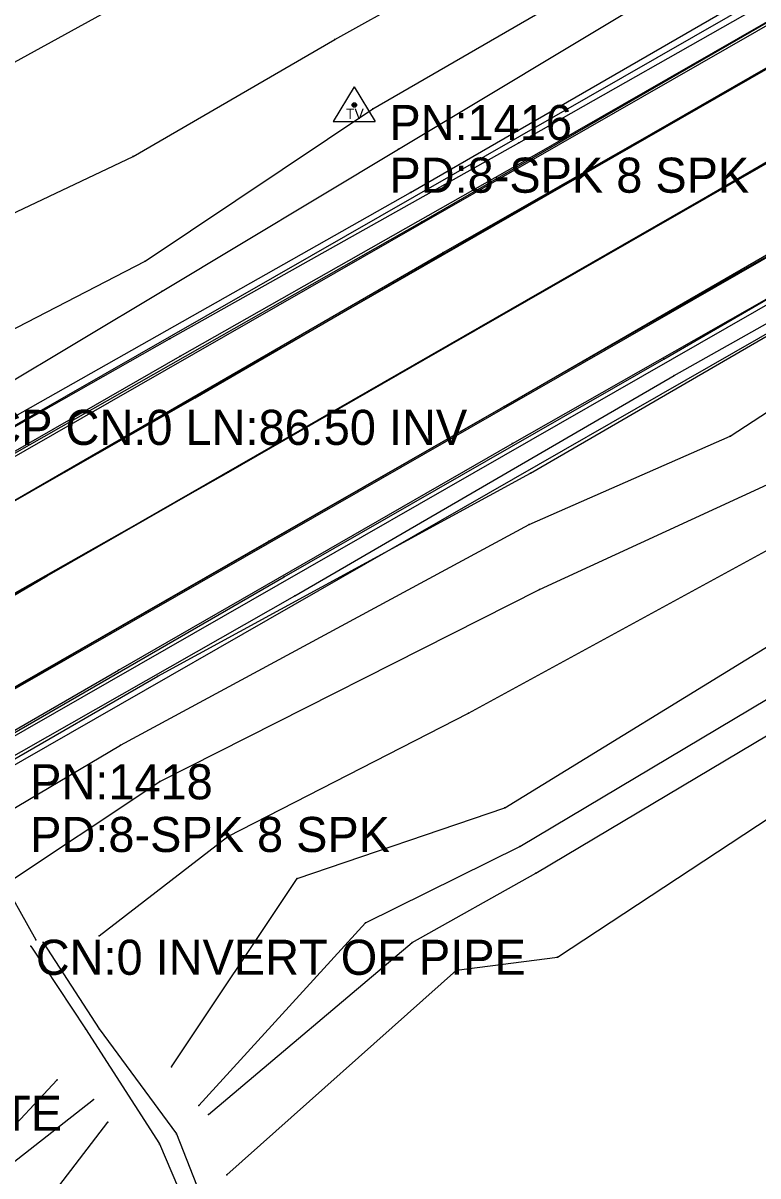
# Model space of a CAD drawing. Extents: x 1419505 to 1434054, y 1956910 to 1968644.
# Drawn here: x 1421962.4 to 1422067.1, y 1958243.6 to 1958407.8 of the extents above; entities that cross this region are included whole.
import ezdxf

# ---------------------------------------------------------------- set-up
doc = ezdxf.new("R2010")
doc.units = 0
for name, color, linetype in [('S_BREAKLINE', 7, 'Continuous'), ('S_CROSS_DRAIN', 7, 'Continuous'), ('S_CROSS_DRAIN_ANNOT', 7, 'Continuous'), ('S_DITCHLINE', 7, 'Continuous'), ('S_DRG_PT_SYM', 7, 'Continuous'), ('S_EDGE_PAVEMENT', 7, 'Continuous'), ('S_GRD_PT_SYM', 7, 'Continuous'), ('S_PAVEMENT_CROWN', 7, 'Continuous'), ('S_RDW_PT_SYM', 7, 'Continuous'), ('S_SECONDARY_CTL', 7, 'Continuous'), ('S_SECONDARY_CTL_ANNOT', 7, 'Continuous'), ('S_SHOULDER', 7, 'Continuous'), ('S_UTILITY_POLE_ANNOT', 7, 'Continuous')]:
    doc.layers.add(name, color=color, linetype=linetype)

msp = doc.modelspace()

# ---------------------------------------------------------------- linework, layer by layer
at = {"layer": 'S_BREAKLINE'}
for p, q in [((1422234.7195, 1958507.1234), (1421697.9208, 1958199.8056)), ((1422256.1529, 1958471.0691), (1421717.7711, 1958162.8162)), ((1422006.7898, 1958405.5229), (1422053.5668, 1958431.4825)), ((1422012.2361, 1958395.6072), (1422059.3222, 1958422.91)), ((1421917.104, 1958378.0281), (1421994.628, 1958420.6969)), ((1422033.0325, 1958390.7609), (1422085.1288, 1958420.3518)), ((1422015.8844, 1958389.8979), (1422062.5334, 1958417.8917)), ((1422017.6015, 1958383.6815), (1422073.1751, 1958415.8125)), ((1421978.0419, 1958388.8168), (1422006.7898, 1958405.5229)), ((1421979.78, 1958373.9038), (1422012.2361, 1958395.6072)), ((1421983.2653, 1958362.8431), (1422033.0325, 1958390.7609)), ((1421982.2072, 1958369.6576), (1422015.8844, 1958389.8979)), ((1421958.5247, 1958379.5882), (1421978.0419, 1958388.8168)), ((1422055.1799, 1958357.6138), (1422103.028, 1958384.7115)), ((1421954.2254, 1958347.8811), (1422017.6015, 1958383.6815)), ((1422063.1634, 1958348.9762), (1422110.2245, 1958379.8242)), ((1422034.6836, 1958343.7029), (1422093.6324, 1958377.9281)), ((1421937.4223, 1958352.1054), (1421979.78, 1958373.9038)), ((1421938.5364, 1958343.5369), (1421982.2072, 1958369.6576)), ((1421931.9739, 1958333.7802), (1421983.2653, 1958362.8431)), ((1422001.1034, 1958326.2257), (1422055.1799, 1958357.6138)), ((1422034.4776, 1958336.4084), (1422063.1634, 1958348.9762)), ((1421981.5771, 1958314.819), (1422034.6836, 1958343.7029)), ((1422035.9747, 1958327.1518), (1422068.4648, 1958342.0838)), ((1421976.2538, 1958304.9524), (1422034.4776, 1958336.4084)), ((1422025.847, 1958309.5217), (1422071.824, 1958334.6333)), ((1421981.8452, 1958299.808), (1422035.9747, 1958327.1518)), ((1421952.7093, 1958298.741), (1422001.1034, 1958326.2257)), ((1422031.0383, 1958296.0688), (1422080.2205, 1958326.2678)), ((1421916.0939, 1958277.0146), (1421981.5771, 1958314.819)), ((1422038.5128, 1958274.7904), (1422097.1516, 1958313.3479)), ((1421991.5588, 1958291.9495), (1422025.847, 1958309.5217)), ((1421948.47, 1958288.4943), (1421976.2538, 1958304.9524)), ((1421952.6123, 1958280.3578), (1421981.8452, 1958299.808)), ((1422001.4264, 1958285.9711), (1422031.0383, 1958296.0688)), ((1421973.2386, 1958277.8106), (1421991.5588, 1958291.9495)), ((1421983.5273, 1958259.1464), (1422001.4264, 1958285.9711)), ((1422024.1189, 1958272.9393), (1422038.5128, 1958274.7904)), ((1421991.4308, 1958243.7604), (1422024.1189, 1958272.9393)), ((1421953.8624, 1958242.9624), (1421967.2182, 1958257.3113))]:
    msp.add_line(p, q, dxfattribs=at)
at = {"layer": 'S_CROSS_DRAIN'}
msp.add_line((1421921.8453, 1958352.7455), (1421964.179, 1958277.2576), dxfattribs=at)
at = {"layer": 'S_DITCHLINE'}
for p, q in [((1422033.1765, 1958290.5544), (1422085.0588, 1958321.4514)), ((1422035.4296, 1958286.7462), (1422088.245, 1958318.1782)), ((1422011.1851, 1958279.6487), (1422033.1765, 1958290.5544)), ((1422017.8235, 1958276.8446), (1422035.4296, 1958286.7462)), ((1421987.4345, 1958253.6431), (1422011.1851, 1958279.6487)), ((1421963.46, 1958276.3395), (1421971.2655, 1958264.5638)), ((1421965.2461, 1958276.8846), (1421973.2396, 1958264.5658)), ((1421988.7896, 1958252.364), (1422017.8235, 1958276.8446)), ((1421971.2655, 1958264.5638), (1421981.7942, 1958248.1677)), ((1421973.2396, 1958264.5658), (1421984.2623, 1958249.5828)), ((1421959.2047, 1958244.1254), (1421972.3946, 1958254.4791)), ((1421963.978, 1958237.6), (1421974.4557, 1958251.2699)), ((1421984.2623, 1958249.5828), (1421988.8426, 1958237.869)), ((1421981.7942, 1958248.1677), (1421986.8055, 1958236.563))]:
    msp.add_line(p, q, dxfattribs=at)
at = {"layer": 'S_DRG_PT_SYM'}
msp.add_lwpolyline([(1421964.179, 1958277.2576), (1421964.179, 1958277.3076), (1421964.179, 1958277.2576), (1421964.129, 1958277.2576), (1421964.179, 1958277.2576), (1421964.179, 1958277.2076), (1421964.179, 1958277.2576), (1421964.229, 1958277.2576)], dxfattribs=at)
at = {"layer": 'S_EDGE_PAVEMENT'}
for p, q in [((1422239.4358, 1958499.3739), (1421702.5421, 1958191.435)), ((1422250.9195, 1958479.1606), (1421712.8678, 1958170.5937)), ((1422037.8508, 1958384.0085), (1422088.5001, 1958413.0854)), ((1422022.2428, 1958375.1419), (1422077.7144, 1958406.7339)), ((1422050.5066, 1958364.4322), (1422098.1177, 1958391.499)), ((1422030.9553, 1958353.2065), (1422088.8241, 1958386.7197)), ((1421986.8895, 1958354.4306), (1422037.8508, 1958384.0085)), ((1421960.3158, 1958339.3426), (1422022.2428, 1958375.1419)), ((1421997.4022, 1958334.0293), (1422050.5066, 1958364.4322)), ((1421937.4303, 1958326.3088), (1421986.8895, 1958354.4306)), ((1421972.0725, 1958319.4363), (1422030.9553, 1958353.2065)), ((1421948.429, 1958305.9944), (1421997.4022, 1958334.0293)), ((1421913.0017, 1958285.5141), (1421972.0725, 1958319.4363))]:
    msp.add_line(p, q, dxfattribs=at)
at = {"layer": 'S_GRD_PT_SYM'}
for points in [[(1422006.7898, 1958405.5229), (1422006.7898, 1958405.5729), (1422006.7898, 1958405.5229), (1422006.7398, 1958405.5229), (1422006.7898, 1958405.5229), (1422006.7898, 1958405.4729), (1422006.7898, 1958405.5229), (1422006.8398, 1958405.5229)], [(1422012.2361, 1958395.6072), (1422012.2361, 1958395.6572), (1422012.2361, 1958395.6072), (1422012.1861, 1958395.6072), (1422012.2361, 1958395.6072), (1422012.2361, 1958395.5572), (1422012.2361, 1958395.6072), (1422012.2861, 1958395.6072)], [(1422033.0325, 1958390.7609), (1422033.0325, 1958390.8109), (1422033.0325, 1958390.7609), (1422032.9825, 1958390.7609), (1422033.0325, 1958390.7609), (1422033.0325, 1958390.7109), (1422033.0325, 1958390.7609), (1422033.0825, 1958390.7609)], [(1422015.8844, 1958389.8979), (1422015.8844, 1958389.9479), (1422015.8844, 1958389.8979), (1422015.8344, 1958389.8979), (1422015.8844, 1958389.8979), (1422015.8844, 1958389.8479), (1422015.8844, 1958389.8979), (1422015.9344, 1958389.8979)], [(1421978.0419, 1958388.8168), (1421978.0419, 1958388.8668), (1421978.0419, 1958388.8168), (1421977.9919, 1958388.8168), (1421978.0419, 1958388.8168), (1421978.0419, 1958388.7668), (1421978.0419, 1958388.8168), (1421978.0919, 1958388.8168)], [(1422017.6015, 1958383.6815), (1422017.6015, 1958383.7315), (1422017.6015, 1958383.6815), (1422017.5515, 1958383.6815), (1422017.6015, 1958383.6815), (1422017.6015, 1958383.6315), (1422017.6015, 1958383.6815), (1422017.6515, 1958383.6815)], [(1421979.78, 1958373.9038), (1421979.78, 1958373.9538), (1421979.78, 1958373.9038), (1421979.73, 1958373.9038), (1421979.78, 1958373.9038), (1421979.78, 1958373.8538), (1421979.78, 1958373.9038), (1421979.83, 1958373.9038)], [(1421982.2072, 1958369.6576), (1421982.2072, 1958369.7076), (1421982.2072, 1958369.6576), (1421982.1572, 1958369.6576), (1421982.2072, 1958369.6576), (1421982.2072, 1958369.6076), (1421982.2072, 1958369.6576), (1421982.2572, 1958369.6576)], [(1421983.2653, 1958362.8431), (1421983.2653, 1958362.8931), (1421983.2653, 1958362.8431), (1421983.2153, 1958362.8431), (1421983.2653, 1958362.8431), (1421983.2653, 1958362.7931), (1421983.2653, 1958362.8431), (1421983.3153, 1958362.8431)], [(1422055.1799, 1958357.6138), (1422055.1799, 1958357.6638), (1422055.1799, 1958357.6138), (1422055.1299, 1958357.6138), (1422055.1799, 1958357.6138), (1422055.1799, 1958357.5638), (1422055.1799, 1958357.6138), (1422055.2299, 1958357.6138)], [(1422063.1634, 1958348.9762), (1422063.1634, 1958349.0262), (1422063.1634, 1958348.9762), (1422063.1134, 1958348.9762), (1422063.1634, 1958348.9762), (1422063.1634, 1958348.9262), (1422063.1634, 1958348.9762), (1422063.2134, 1958348.9762)], [(1422034.6836, 1958343.7029), (1422034.6836, 1958343.7529), (1422034.6836, 1958343.7029), (1422034.6336, 1958343.7029), (1422034.6836, 1958343.7029), (1422034.6836, 1958343.6529), (1422034.6836, 1958343.7029), (1422034.7336, 1958343.7029)], [(1422034.4776, 1958336.4084), (1422034.4776, 1958336.4584), (1422034.4776, 1958336.4084), (1422034.4276, 1958336.4084), (1422034.4776, 1958336.4084), (1422034.4776, 1958336.3584), (1422034.4776, 1958336.4084), (1422034.5276, 1958336.4084)], [(1422035.9747, 1958327.1518), (1422035.9747, 1958327.2018), (1422035.9747, 1958327.1518), (1422035.9247, 1958327.1518), (1422035.9747, 1958327.1518), (1422035.9747, 1958327.1018), (1422035.9747, 1958327.1518), (1422036.0247, 1958327.1518)], [(1422001.1034, 1958326.2257), (1422001.1034, 1958326.2757), (1422001.1034, 1958326.2257), (1422001.0534, 1958326.2257), (1422001.1034, 1958326.2257), (1422001.1034, 1958326.1757), (1422001.1034, 1958326.2257), (1422001.1534, 1958326.2257)], [(1421981.5771, 1958314.819), (1421981.5771, 1958314.869), (1421981.5771, 1958314.819), (1421981.5271, 1958314.819), (1421981.5771, 1958314.819), (1421981.5771, 1958314.769), (1421981.5771, 1958314.819), (1421981.6271, 1958314.819)], [(1422025.847, 1958309.5217), (1422025.847, 1958309.5717), (1422025.847, 1958309.5217), (1422025.797, 1958309.5217), (1422025.847, 1958309.5217), (1422025.847, 1958309.4717), (1422025.847, 1958309.5217), (1422025.897, 1958309.5217)], [(1421976.2538, 1958304.9524), (1421976.2538, 1958305.0024), (1421976.2538, 1958304.9524), (1421976.2038, 1958304.9524), (1421976.2538, 1958304.9524), (1421976.2538, 1958304.9024), (1421976.2538, 1958304.9524), (1421976.3038, 1958304.9524)], [(1421981.8452, 1958299.808), (1421981.8452, 1958299.858), (1421981.8452, 1958299.808), (1421981.7952, 1958299.808), (1421981.8452, 1958299.808), (1421981.8452, 1958299.758), (1421981.8452, 1958299.808), (1421981.8952, 1958299.808)], [(1422031.0383, 1958296.0688), (1422031.0383, 1958296.1188), (1422031.0383, 1958296.0688), (1422030.9883, 1958296.0688), (1422031.0383, 1958296.0688), (1422031.0383, 1958296.0188), (1422031.0383, 1958296.0688), (1422031.0883, 1958296.0688)], [(1421991.5588, 1958291.9495), (1421991.5588, 1958291.9995), (1421991.5588, 1958291.9495), (1421991.5088, 1958291.9495), (1421991.5588, 1958291.9495), (1421991.5588, 1958291.8995), (1421991.5588, 1958291.9495), (1421991.6088, 1958291.9495)], [(1422033.1765, 1958290.5544), (1422033.1765, 1958290.6044), (1422033.1765, 1958290.5544), (1422033.1265, 1958290.5544), (1422033.1765, 1958290.5544), (1422033.1765, 1958290.5044), (1422033.1765, 1958290.5544), (1422033.2265, 1958290.5544)], [(1422001.4264, 1958285.9711), (1422001.4264, 1958286.0211), (1422001.4264, 1958285.9711), (1422001.3764, 1958285.9711), (1422001.4264, 1958285.9711), (1422001.4264, 1958285.9211), (1422001.4264, 1958285.9711), (1422001.4764, 1958285.9711)], [(1422035.4296, 1958286.7462), (1422035.4296, 1958286.7962), (1422035.4296, 1958286.7462), (1422035.3796, 1958286.7462), (1422035.4296, 1958286.7462), (1422035.4296, 1958286.6962), (1422035.4296, 1958286.7462), (1422035.4796, 1958286.7462)], [(1422011.1851, 1958279.6487), (1422011.1851, 1958279.6987), (1422011.1851, 1958279.6487), (1422011.1351, 1958279.6487), (1422011.1851, 1958279.6487), (1422011.1851, 1958279.5987), (1422011.1851, 1958279.6487), (1422011.2351, 1958279.6487)], [(1421973.2386, 1958277.8106), (1421973.2386, 1958277.8606), (1421973.2386, 1958277.8106), (1421973.1886, 1958277.8106), (1421973.2386, 1958277.8106), (1421973.2386, 1958277.7606), (1421973.2386, 1958277.8106), (1421973.2886, 1958277.8106)], [(1421963.46, 1958276.3395), (1421963.46, 1958276.3895), (1421963.46, 1958276.3395), (1421963.41, 1958276.3395), (1421963.46, 1958276.3395), (1421963.46, 1958276.2895), (1421963.46, 1958276.3395), (1421963.51, 1958276.3395)], [(1421965.2461, 1958276.8846), (1421965.2461, 1958276.9346), (1421965.2461, 1958276.8846), (1421965.1961, 1958276.8846), (1421965.2461, 1958276.8846), (1421965.2461, 1958276.8346), (1421965.2461, 1958276.8846), (1421965.2961, 1958276.8846)], [(1422017.8235, 1958276.8446), (1422017.8235, 1958276.8946), (1422017.8235, 1958276.8446), (1422017.7735, 1958276.8446), (1422017.8235, 1958276.8446), (1422017.8235, 1958276.7946), (1422017.8235, 1958276.8446), (1422017.8735, 1958276.8446)], [(1422038.5128, 1958274.7904), (1422038.5128, 1958274.8404), (1422038.5128, 1958274.7904), (1422038.4628, 1958274.7904), (1422038.5128, 1958274.7904), (1422038.5128, 1958274.7404), (1422038.5128, 1958274.7904), (1422038.5628, 1958274.7904)], [(1422024.1189, 1958272.9393), (1422024.1189, 1958272.9893), (1422024.1189, 1958272.9393), (1422024.0689, 1958272.9393), (1422024.1189, 1958272.9393), (1422024.1189, 1958272.8893), (1422024.1189, 1958272.9393), (1422024.1689, 1958272.9393)], [(1421971.2655, 1958264.5638), (1421971.2655, 1958264.6138), (1421971.2655, 1958264.5638), (1421971.2155, 1958264.5638), (1421971.2655, 1958264.5638), (1421971.2655, 1958264.5138), (1421971.2655, 1958264.5638), (1421971.3155, 1958264.5638)], [(1421973.2396, 1958264.5658), (1421973.2396, 1958264.6158), (1421973.2396, 1958264.5658), (1421973.1896, 1958264.5658), (1421973.2396, 1958264.5658), (1421973.2396, 1958264.5158), (1421973.2396, 1958264.5658), (1421973.2896, 1958264.5658)], [(1421983.5273, 1958259.1464), (1421983.5273, 1958259.1964), (1421983.5273, 1958259.1464), (1421983.4773, 1958259.1464), (1421983.5273, 1958259.1464), (1421983.5273, 1958259.0964), (1421983.5273, 1958259.1464), (1421983.5773, 1958259.1464)], [(1421967.2182, 1958257.3113), (1421967.2182, 1958257.3613), (1421967.2182, 1958257.3113), (1421967.1682, 1958257.3113), (1421967.2182, 1958257.3113), (1421967.2182, 1958257.2613), (1421967.2182, 1958257.3113), (1421967.2682, 1958257.3113)], [(1421972.3946, 1958254.4791), (1421972.3946, 1958254.5291), (1421972.3946, 1958254.4791), (1421972.3446, 1958254.4791), (1421972.3946, 1958254.4791), (1421972.3946, 1958254.4291), (1421972.3946, 1958254.4791), (1421972.4446, 1958254.4791)], [(1421987.4345, 1958253.6431), (1421987.4345, 1958253.6931), (1421987.4345, 1958253.6431), (1421987.3845, 1958253.6431), (1421987.4345, 1958253.6431), (1421987.4345, 1958253.5931), (1421987.4345, 1958253.6431), (1421987.4845, 1958253.6431)], [(1421974.4557, 1958251.2699), (1421974.4557, 1958251.3199), (1421974.4557, 1958251.2699), (1421974.4057, 1958251.2699), (1421974.4557, 1958251.2699), (1421974.4557, 1958251.2199), (1421974.4557, 1958251.2699), (1421974.5057, 1958251.2699)], [(1421988.7896, 1958252.364), (1421988.7896, 1958252.414), (1421988.7896, 1958252.364), (1421988.7396, 1958252.364), (1421988.7896, 1958252.364), (1421988.7896, 1958252.314), (1421988.7896, 1958252.364), (1421988.8396, 1958252.364)], [(1421984.2623, 1958249.5828), (1421984.2623, 1958249.6328), (1421984.2623, 1958249.5828), (1421984.2123, 1958249.5828), (1421984.2623, 1958249.5828), (1421984.2623, 1958249.5328), (1421984.2623, 1958249.5828), (1421984.3123, 1958249.5828)], [(1421981.7942, 1958248.1677), (1421981.7942, 1958248.2177), (1421981.7942, 1958248.1677), (1421981.7442, 1958248.1677), (1421981.7942, 1958248.1677), (1421981.7942, 1958248.1177), (1421981.7942, 1958248.1677), (1421981.8442, 1958248.1677)], [(1421991.4308, 1958243.7604), (1421991.4308, 1958243.8104), (1421991.4308, 1958243.7604), (1421991.3808, 1958243.7604), (1421991.4308, 1958243.7604), (1421991.4308, 1958243.7104), (1421991.4308, 1958243.7604), (1421991.4808, 1958243.7604)]]:
    msp.add_lwpolyline(points, dxfattribs=at)
at = {"layer": 'S_PAVEMENT_CROWN'}
for p, q in [((1422245.2512, 1958489.5463), (1421708.2975, 1958181.3584)), ((1422043.7072, 1958373.7848), (1422093.1814, 1958402.4757)), ((1422026.7281, 1958363.9952), (1422083.2277, 1958396.4123)), ((1421991.6488, 1958343.8719), (1422043.7072, 1958373.7848)), ((1421965.8041, 1958329.0769), (1422026.7281, 1958363.9952)), ((1421942.7396, 1958316.2111), (1421991.6488, 1958343.8719)), ((1421910.2865, 1958296.6928), (1421965.8041, 1958329.0769))]:
    msp.add_line(p, q, dxfattribs=at)
at = {"layer": 'S_RDW_PT_SYM'}
for points in [[(1422034.6106, 1958388.6498), (1422034.6106, 1958388.6998), (1422034.6106, 1958388.6498), (1422034.5606, 1958388.6498), (1422034.6106, 1958388.6498), (1422034.6106, 1958388.5998), (1422034.6106, 1958388.6498), (1422034.6606, 1958388.6498)], [(1422037.8508, 1958384.0085), (1422037.8508, 1958384.0585), (1422037.8508, 1958384.0085), (1422037.8008, 1958384.0085), (1422037.8508, 1958384.0085), (1422037.8508, 1958383.9585), (1422037.8508, 1958384.0085), (1422037.9008, 1958384.0085)], [(1422019.2166, 1958379.5102), (1422019.2166, 1958379.5602), (1422019.2166, 1958379.5102), (1422019.1666, 1958379.5102), (1422019.2166, 1958379.5102), (1422019.2166, 1958379.4602), (1422019.2166, 1958379.5102), (1422019.2666, 1958379.5102)], [(1422022.2428, 1958375.1419), (1422022.2428, 1958375.1919), (1422022.2428, 1958375.1419), (1422022.1928, 1958375.1419), (1422022.2428, 1958375.1419), (1422022.2428, 1958375.0919), (1422022.2428, 1958375.1419), (1422022.2928, 1958375.1419)], [(1422043.7072, 1958373.7848), (1422043.7072, 1958373.8348), (1422043.7072, 1958373.7848), (1422043.6572, 1958373.7848), (1422043.7072, 1958373.7848), (1422043.7072, 1958373.7348), (1422043.7072, 1958373.7848), (1422043.7572, 1958373.7848)], [(1422050.5066, 1958364.4322), (1422050.5066, 1958364.4822), (1422050.5066, 1958364.4322), (1422050.4566, 1958364.4322), (1422050.5066, 1958364.4322), (1422050.5066, 1958364.3822), (1422050.5066, 1958364.4322), (1422050.5566, 1958364.4322)], [(1422026.7281, 1958363.9952), (1422026.7281, 1958364.0452), (1422026.7281, 1958363.9952), (1422026.6781, 1958363.9952), (1422026.7281, 1958363.9952), (1422026.7281, 1958363.9452), (1422026.7281, 1958363.9952), (1422026.7781, 1958363.9952)], [(1421984.7564, 1958360.397), (1421984.7564, 1958360.447), (1421984.7564, 1958360.397), (1421984.7064, 1958360.397), (1421984.7564, 1958360.397), (1421984.7564, 1958360.347), (1421984.7564, 1958360.397), (1421984.8064, 1958360.397)], [(1422053.6768, 1958359.9559), (1422053.6768, 1958360.0059), (1422053.6768, 1958359.9559), (1422053.6268, 1958359.9559), (1422053.6768, 1958359.9559), (1422053.6768, 1958359.9059), (1422053.6768, 1958359.9559), (1422053.7268, 1958359.9559)], [(1421986.8895, 1958354.4306), (1421986.8895, 1958354.4806), (1421986.8895, 1958354.4306), (1421986.8395, 1958354.4306), (1421986.8895, 1958354.4306), (1421986.8895, 1958354.3806), (1421986.8895, 1958354.4306), (1421986.9395, 1958354.4306)], [(1422030.9553, 1958353.2065), (1422030.9553, 1958353.2565), (1422030.9553, 1958353.2065), (1422030.9053, 1958353.2065), (1422030.9553, 1958353.2065), (1422030.9553, 1958353.1565), (1422030.9553, 1958353.2065), (1422031.0053, 1958353.2065)], [(1422032.1004, 1958347.9462), (1422032.1004, 1958347.9962), (1422032.1004, 1958347.9462), (1422032.0504, 1958347.9462), (1422032.1004, 1958347.9462), (1422032.1004, 1958347.8962), (1422032.1004, 1958347.9462), (1422032.1504, 1958347.9462)], [(1421991.6488, 1958343.8719), (1421991.6488, 1958343.9219), (1421991.6488, 1958343.8719), (1421991.5988, 1958343.8719), (1421991.6488, 1958343.8719), (1421991.6488, 1958343.8219), (1421991.6488, 1958343.8719), (1421991.6988, 1958343.8719)], [(1421997.4022, 1958334.0293), (1421997.4022, 1958334.0793), (1421997.4022, 1958334.0293), (1421997.3522, 1958334.0293), (1421997.4022, 1958334.0293), (1421997.4022, 1958333.9793), (1421997.4022, 1958334.0293), (1421997.4522, 1958334.0293)], [(1421965.8041, 1958329.0769), (1421965.8041, 1958329.1269), (1421965.8041, 1958329.0769), (1421965.7541, 1958329.0769), (1421965.8041, 1958329.0769), (1421965.8041, 1958329.0269), (1421965.8041, 1958329.0769), (1421965.8541, 1958329.0769)], [(1421999.6003, 1958328.9599), (1421999.6003, 1958329.0099), (1421999.6003, 1958328.9599), (1421999.5503, 1958328.9599), (1421999.6003, 1958328.9599), (1421999.6003, 1958328.9099), (1421999.6003, 1958328.9599), (1421999.6503, 1958328.9599)], [(1421972.0725, 1958319.4363), (1421972.0725, 1958319.4863), (1421972.0725, 1958319.4363), (1421972.0225, 1958319.4363), (1421972.0725, 1958319.4363), (1421972.0725, 1958319.3863), (1421972.0725, 1958319.4363), (1421972.1225, 1958319.4363)], [(1421975.9918, 1958315.6651), (1421975.9918, 1958315.7151), (1421975.9918, 1958315.6651), (1421975.9418, 1958315.6651), (1421975.9918, 1958315.6651), (1421975.9918, 1958315.6151), (1421975.9918, 1958315.6651), (1421976.0418, 1958315.6651)]]:
    msp.add_lwpolyline(points, dxfattribs=at)
at = {"layer": 'S_SECONDARY_CTL'}
for p, q in [((1422009.581, 1958398.7794), (1422006.571, 1958393.8255)), ((1422009.581, 1958398.7794), (1422012.5283, 1958393.8255)), ((1422006.571, 1958393.8255), (1422012.5283, 1958393.8255))]:
    msp.add_line(p, q, dxfattribs=at)
for radius in [0.3111, 0.1827, 0.1033]:
    msp.add_circle((1422009.581, 1958396.1693), radius, dxfattribs=at)
at = {"layer": 'S_SHOULDER'}
for p, q in [((1422236.8876, 1958504.0772), (1421699.4589, 1958196.0923)), ((1422254.1918, 1958474.1573), (1421715.306, 1958165.4004)), ((1422034.6106, 1958388.6498), (1422086.2219, 1958418.2657)), ((1422019.2166, 1958379.5102), (1422075.2692, 1958411.9093)), ((1421984.7564, 1958360.397), (1422034.6106, 1958388.6498)), ((1422053.6768, 1958359.9559), (1422101.1489, 1958387.5657)), ((1422032.1004, 1958347.9462), (1422091.3382, 1958381.6133)), ((1421956.4095, 1958343.8829), (1422019.2166, 1958379.5102)), ((1421934.0991, 1958331.3301), (1421984.7564, 1958360.397)), ((1421999.6003, 1958328.9599), (1422053.6768, 1958359.9559)), ((1421975.9918, 1958315.6651), (1422032.1004, 1958347.9462)), ((1421951.5622, 1958301.2411), (1421999.6003, 1958328.9599)), ((1421915.1739, 1958280.4978), (1421975.9918, 1958315.6651))]:
    msp.add_line(p, q, dxfattribs=at)

# ---------------------------------------------------------------- texts
at = {"layer": 'S_CROSS_DRAIN_ANNOT'}
for s, p in [('DI:24" TY:RCP CN:0 LN:86.50 INV', (1421921.8453, 1958347.7455)), ('CN:0 INVERT OF PIPE', (1421964.179, 1958272.2576))]:
    msp.add_text(s, height=5, dxfattribs=at).set_placement(p)
at = {"layer": 'S_SECONDARY_CTL'}
msp.add_text('TV', height=1.5, rotation=360, dxfattribs=at).set_placement((1422008.3763, 1958394.158))
at = {"layer": 'S_SECONDARY_CTL_ANNOT'}
for s, p in [('PN:1416', (1422014.581, 1958391.1693)), ('PD:8-SPK 8 SPK', (1422014.581, 1958383.6693)), ('PN:1418', (1421963.3847, 1958297.2522)), ('PD:8-SPK 8 SPK', (1421963.3847, 1958289.7522))]:
    msp.add_text(s, height=5, dxfattribs=at).set_placement(p)
at = {"layer": 'S_UTILITY_POLE_ANNOT'}
msp.add_text('GTE', height=5, dxfattribs=at).set_placement((1421954.1904, 1958250.0372))

doc.saveas('drawing.dxf')
